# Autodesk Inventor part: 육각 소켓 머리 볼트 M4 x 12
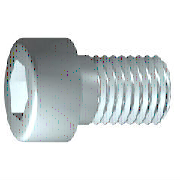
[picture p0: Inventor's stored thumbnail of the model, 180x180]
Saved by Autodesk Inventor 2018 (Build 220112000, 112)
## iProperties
IsCustomPart: 1
Created: 2012-02
Part Number: 육각 소켓 머리 볼트 M4 x 12
Material: 강철, 연강
Description: 6각 소켓 머리 캡 나사
Document SubType Name: Modeling
Standard: ISO 4762
Designer: mdu-01
Standard Revision: Fourth edition 2004-03-01
Standards Organization: ISO
Language: ko-KR
Size Designation: M4 x 12
Categories: <MemberInstance><Categories><Category DisplayName="조임쇠" InternalName="e4da775c-781d-43d5-af7c-5136215cf5a6" Mnemonic="FSTN"><Category DisplayName="볼트" InternalN
Density: 7.75 g/cm^3
Appearance: 강철
Author: mdu-01
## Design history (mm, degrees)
sketch "스케치1"
  geometry: L1 (-1, 0)-(12, 0); L2 (12, 0)-(12, 2); L3 (12, 2)-(1.75, 2); L4 (1.75, 2)-(1.32, 2); L5 (1.32, 2)-(0, 2); L6 (0, 2)-(0, 3.5); L7 (0, 3.5)-(-4, 3.5); L8 (-4, 3.5)-(-4, 1.732); L9 (-4, 1.732)-(-2, 1.732); L10 (-2, 1.732)-(-1, 0); L11 (-7.2, 0)-(15.2, 0) reference; L12 (0, -0.7)-(0, 4.2) reference; L13 (1.75, 2)-(0, 2)
  constraints: 22 end point, 6 parallel, 2 collinear, 2 perpendicular, 1 horizontal, 1 point on line
  dimensions: "d1" = 10.25 distance from line of L3.end L2 (= GEL); "d2" = 0.42952 distance of L4.end L3.end (computed from GAL); "d3" = 4 distance between parallel lines of L8 L6 (= KOH); "d4" = 2 distance of L8.end L9.end (= INTI); "d5" = 60 deg angle of L10 L1; "d6" = 4 diameter of L3 L1 (= GD); "d7" = 4 diameter of L5 L1 (= BDM); "d8" = 3.4641 diameter of L9 L1 (= 1.1547 x SW); "d9" = 7 diameter of L7 L1 (= KOD); "d26" = 12 distance between parallel lines of L12 L2 (= NLG)
revolve "본체" sketch "스케치1" stored, may be unused: angle "d10" = 90 deg
sketch "스케치2"
  geometry: L1 (0, -4.9)-(0, 4.9) reference; L2 (-4.9, 0)-(4.9, 0) reference; L3 (1.732, 0)-(0.866, -1.5); L4 (0.866, -1.5)-(-0.866, -1.5); L5 (-0.866, -1.5)-(-1.732, 0); L6 (-1.732, 0)-(-0.866, 1.5); L7 (-0.866, 1.5)-(0.866, 1.5); L8 (0.866, 1.5)-(1.732, 0); 2 further points
  constraints: 12 end point, 1 coincident, 1 horizontal alignment, 1 point on line, 12 other
extrude "슬롯" join sketch "스케치2" stored distance "d11" = 10; taper "d12" = 0 deg
workplane "Work Plane1"
fillet "Fillet2" dims "d30" = 0.1 (= R)
body "Solid1"
fillet "모깎기1" dims "d17" = 0.4 (= RR)
feature "스레드" dims "d13" = 10.25 (= GEL), "d14" = 0
chamfer "모따기1" distance "d15" = 0.42941 (= -0.5 x SPD + 0.5 x GD); stored, may be unused: second distance "d16" = 0.42941 (= GUL), angle "d27" = 45 deg
other parameters: "GD" = 4 [user parameter; used in 2 equation terms], "NLG" = 12 [user parameter; used in 1 equation term], "GEL" = 10.25 [user parameter; used in 2 equation terms], "KOD" = 7 [user parameter; used in 1 equation term], "KOH" = 4 [user parameter; used in 1 equation term], "INTI" = 2 [user parameter; used in 1 equation term], "GAL" = 0.42941 (= 0.61345 x PTC) [user parameter; used in 1 equation term], "GUL" = 0.42941 (= 0.61345 x PTC) [user parameter; used in 1 equation term], "BDM" = 4 (= NND) [user parameter; used in 1 equation term], "SW" = 3 [user parameter; used in 2 equation terms], "RR" = 0.4 [user parameter; used in 1 equation term], "SPD" = 3.14117 (= NND - 1.2269 x PTC) [user parameter; used in 1 equation term], "d19" = 0, "d28" = 0, "d29" = 0, "R" = 0.1 [user parameter; used in 1 equation term], "TOA" = 30 deg [user parameter], "GD1" = 3.14117 (= THREADDIA - 1.2269 x PTC) [user parameter], "THREADDIA" = 4 [user parameter; used in 1 equation term], "FAWI" = 45 deg [user parameter], "TPU" = 14.28571 (computed from PTC) [user parameter], "PTC" = 0.7 [user parameter; used in 5 equation terms], "NND" = 4 [user parameter; used in 2 equation terms], "E0" = 3.465 (= 1.155 x SW) [user parameter]
